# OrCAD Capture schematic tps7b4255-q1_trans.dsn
size Custom; title: TPS54233 :2A, 28V INPUT, STEP DOWN SWIFT; rev: 1.1; note: SBVS392 - June 2022
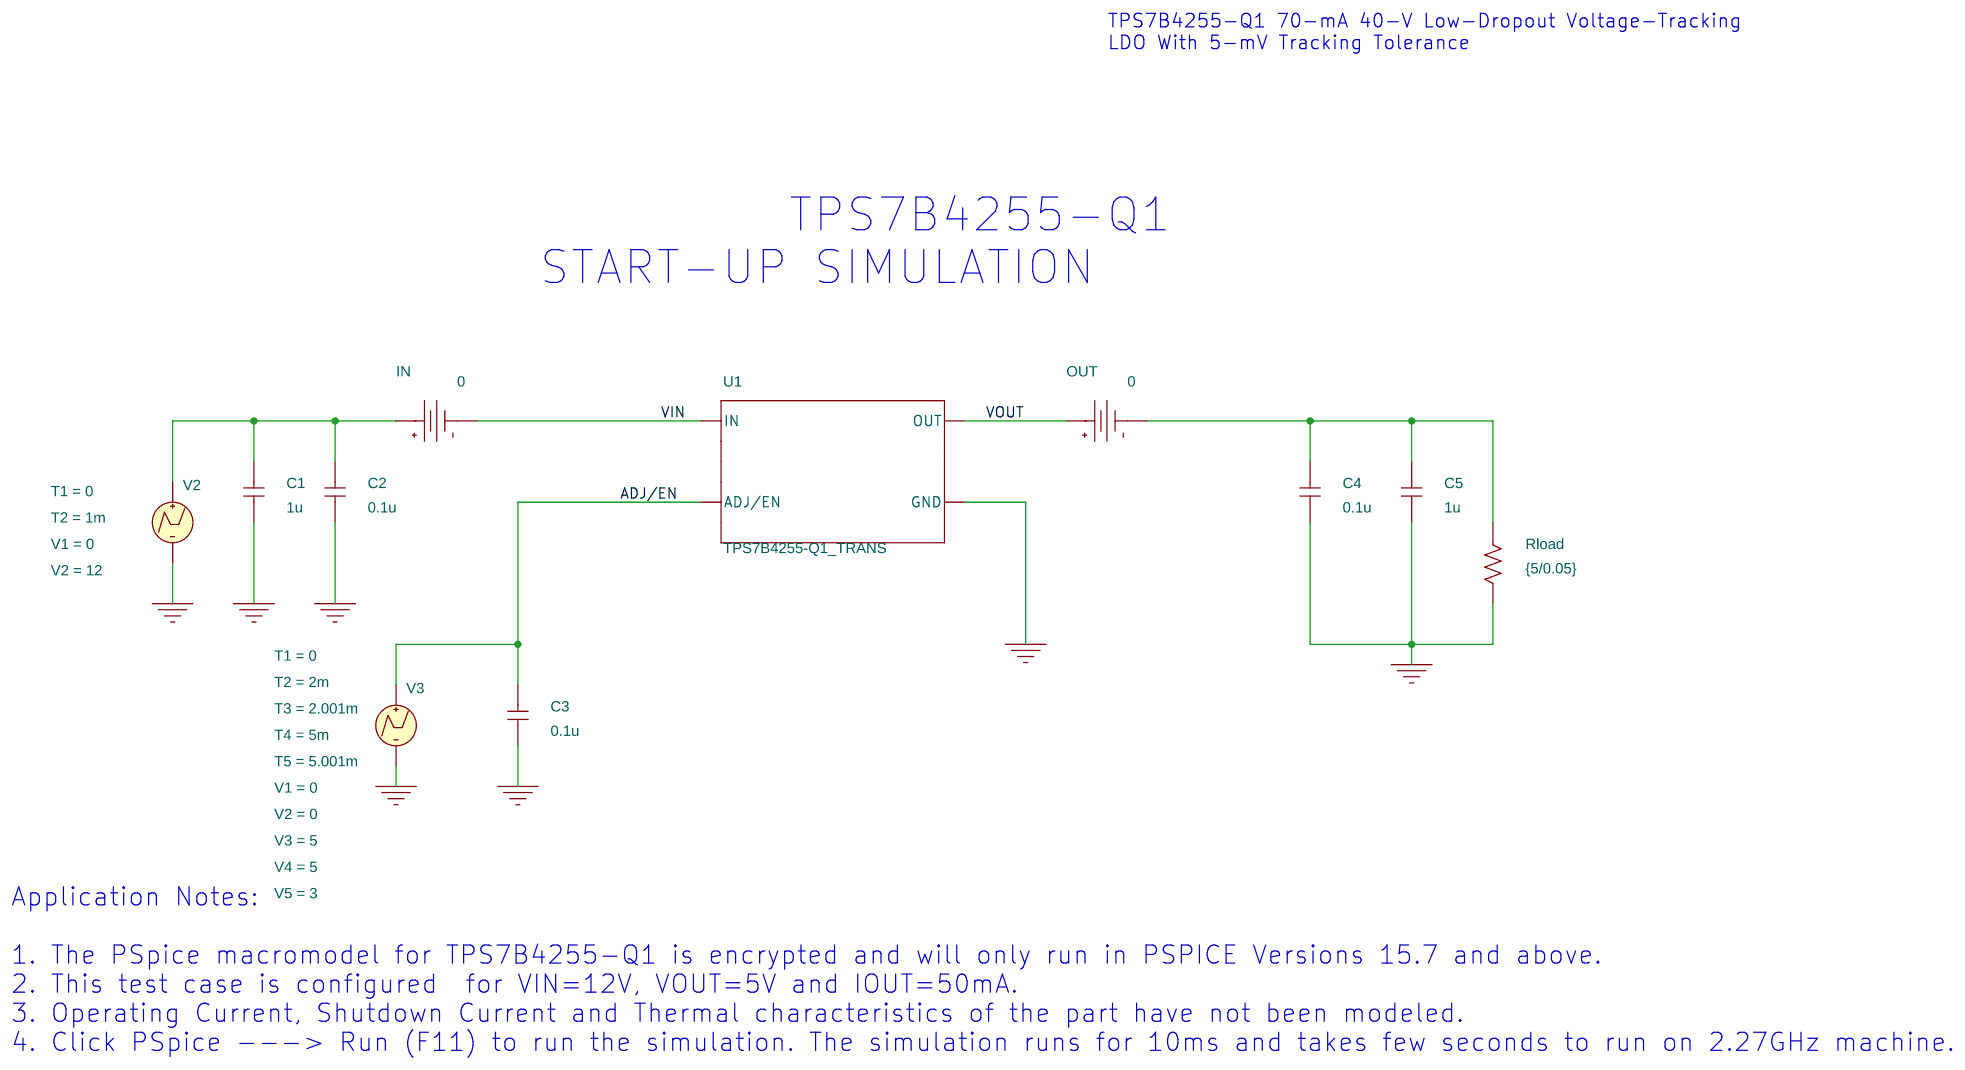
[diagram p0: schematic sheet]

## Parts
C1  1u  [RAD/CK05]
C2  0.1u  [RAD/CK05]
C3  0.1u  [RAD/CK05]
C4  0.1u  [RAD/CK05]
C5  1u  [RAD/CK05]
IN  VDC
OUT  VDC
Rload  {5/0.05}  [AX/RC05]
U1  TPS7B4255-Q1_TRANS
V2  VPWL
V3  VPWL

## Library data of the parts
C1-C5 = C
IN OUT = VDC: DC: 0
Rload = R
U1 = TPS7B4255-Q1_TRANS
V2 = VPWL: T1: 0; T2: 1m; V1: 0; V2: 12
V3 = VPWL: T1: 0; T2: 2m; T3: 2.001m; T4: 5m; T5: 5.001m; V1: 0; V2: 0; V3: 5; V4: 5; V5: 3

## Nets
VIN: IN.1(-) U1.IN
0: C1.2 C2.2 C3.2 C4.2 C5.2 Rload.2 U1.GND V2.2(-) V3.2(-)
ADJ/EN: C3.1 U1.ADJ/EN V3.1(+)
VOUT: OUT.0(+) U1.OUT
N309796: C4.1 C5.1 OUT.1(-) Rload.1
N309868: C1.1 C2.1 IN.0(+) V2.1(+)

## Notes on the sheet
- TPS7B4255-Q1 70-mA 40-V Low-Dropout Voltage-Tracking
  LDO With 5-mV Tracking Tolerance
- TPS7B4255-Q1
  START-UP SIMULATION
- Application Notes:
  1. The PSpice macromodel for TPS7B4255-Q1 is encrypted and will only run in PSPICE Versions 15.7 and above.
  2. This test case is configured  for VIN=12V, VOUT=5V and IOUT=50mA.
  3. Operating Current, Shutdown Current and Thermal characteristics of the part have not been modeled.
  4. Click PSpice ---> Run (F11) to run the simulation. The simulation runs for 10ms and takes few seconds to run on 2.27GHz machine.
